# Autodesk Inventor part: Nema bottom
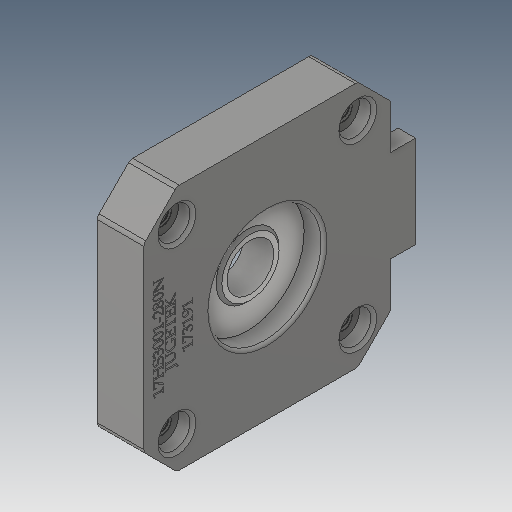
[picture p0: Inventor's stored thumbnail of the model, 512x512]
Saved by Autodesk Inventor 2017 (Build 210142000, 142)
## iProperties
Created: 2018-08
Part Number: Nema bottom
Material: Iron, Ductile
Document SubType Name: Modeling
Designer: JK
Density: 7.15 g/cm^3
Appearance: Iron Gray
Author: JK
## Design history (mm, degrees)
feature "Body1"
body "Solid1"
